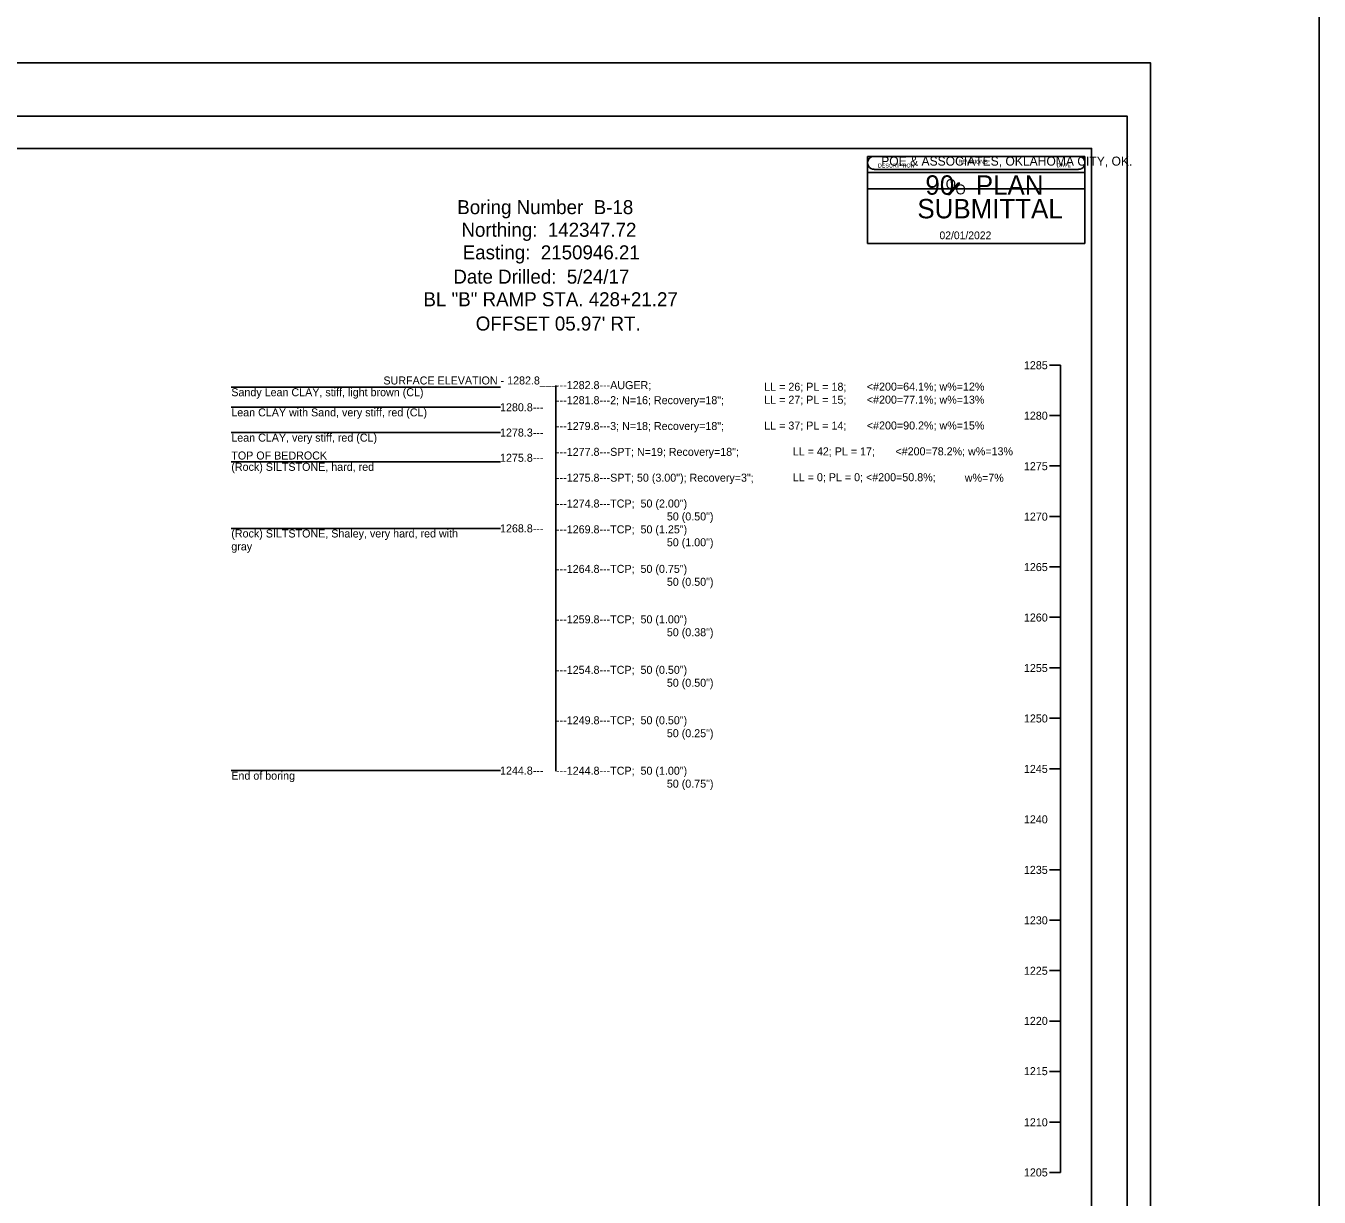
# Model space of a CAD drawing. Extents: x 2150162 to 2150245, y 143729 to 143865.
# Drawn here: x 2150225.21 to 2150245.24, y 143743.1 to 143761.23 of the extents above; entities that cross this region are included whole.
import ezdxf

# ---------------------------------------------------------------- set-up
doc = ezdxf.new("R2010")
doc.units = 0
for name, color, linetype in [('Default', 7, 'Continuous'), ('S', 7, 'Continuous'), ('SHT_Plot_Shape_Full', 7, 'Continuous'), ('SHT_Plot_Shape_Half', 7, 'Continuous'), ('SHT_Sheet_Border', 7, 'Continuous'), ('SHT_Stamp_90_Submit', 7, 'Continuous'), ('SHT_Stamp_Rev_Block', 7, 'Continuous')]:
    doc.layers.add(name, color=color, linetype=linetype)

msp = doc.modelspace()

# ---------------------------------------------------------------- linework, layer by layer
at = {"layer": 'Default'}
msp.add_line((2150241.231, 143743.48), (2150241.231, 143755.98), dxfattribs=at)
for points in [[(2150241.231, 143755.981), (2150241.065, 143755.981)], [(2150228.39, 143755.639), (2150232.557, 143755.639)], [(2150233.416, 143755.664), (2150233.416, 143749.695)], [(2150228.39, 143755.327), (2150232.557, 143755.327)], [(2150241.231, 143755.2), (2150241.065, 143755.2)], [(2150228.39, 143754.936), (2150232.557, 143754.936)], [(2150228.39, 143754.484), (2150232.557, 143754.484)], [(2150241.231, 143754.419), (2150241.065, 143754.419)], [(2150241.231, 143754.419), (2150241.065, 143754.419)], [(2150241.231, 143753.637), (2150241.065, 143753.637)], [(2150228.39, 143753.452), (2150232.557, 143753.452)], [(2150241.231, 143752.856), (2150241.065, 143752.856)], [(2150241.231, 143752.075), (2150241.065, 143752.075)], [(2150241.231, 143751.294), (2150241.065, 143751.294)], [(2150241.231, 143750.512), (2150241.065, 143750.512)], [(2150228.39, 143749.702), (2150232.557, 143749.702)], [(2150241.231, 143749.731), (2150241.065, 143749.731)], [(2150241.231, 143748.167), (2150241.065, 143748.167)], [(2150241.231, 143747.386), (2150241.065, 143747.386)], [(2150241.231, 143746.605), (2150241.065, 143746.605)], [(2150241.231, 143745.823), (2150241.065, 143745.823)], [(2150241.231, 143745.042), (2150241.065, 143745.042)], [(2150241.231, 143744.261), (2150241.065, 143744.261)], [(2150241.231, 143743.48), (2150241.065, 143743.48)]]:
    msp.add_lwpolyline(points, dxfattribs=at)
at = {"layer": 'S'}
msp.add_lwpolyline([(2150203.404, 143865.061), (2150245.24, 143865.061), (2150245.24, 143729.315), (2150203.404, 143729.315)], close=True, dxfattribs=at)
at = {"layer": 'SHT_Plot_Shape_Full'}
msp.add_lwpolyline([(2150206.628, 143760.659), (2150242.628, 143760.659), (2150242.628, 143736.659), (2150206.628, 143736.659)], close=True, dxfattribs=at)
at = {"layer": 'SHT_Plot_Shape_Half'}
msp.add_lwpolyline([(2150208.265, 143759.835), (2150242.265, 143759.835), (2150242.265, 143737.835), (2150208.265, 143737.835)], close=True, dxfattribs=at)
at = {"layer": 'SHT_Sheet_Border'}
msp.add_lwpolyline([(2150241.715, 143738.335), (2150210.215, 143738.335), (2150210.215, 143759.335), (2150241.715, 143759.335)], close=True, dxfattribs=at)
at = {"layer": 'SHT_Stamp_90_Submit'}
for p, q in [((2150238.346, 143759.21), (2150241.512, 143759.21)), ((2150238.246, 143758.96), (2150241.612, 143758.96)), ((2150238.246, 143757.861), (2150238.246, 143758.96)), ((2150238.346, 143759.01), (2150241.512, 143759.01)), ((2150241.612, 143757.861), (2150241.612, 143758.96)), ((2150239.489, 143758.622), (2150239.645, 143758.795)), ((2150239.507, 143758.622), (2150239.662, 143758.795)), ((2150239.512, 143758.622), (2150239.667, 143758.795)), ((2150239.52, 143758.622), (2150239.675, 143758.795)), ((2150239.645, 143758.795), (2150239.675, 143758.795)), ((2150239.489, 143758.622), (2150239.52, 143758.622)), ((2150238.246, 143757.861), (2150241.612, 143757.861))]:
    msp.add_line(p, q, dxfattribs=at)
for centre, start, end in [((2150238.346, 143759.111), 89.9952, 270), ((2150241.512, 143759.111), 270, 90.0048)]:
    msp.add_arc(centre, 0.1, start, end, dxfattribs=at)
at = {"layer": 'SHT_Stamp_Rev_Block'}
for p, q in [((2150238.246, 143759.21), (2150238.246, 143758.71)), ((2150241.612, 143759.21), (2150238.246, 143759.21)), ((2150241.612, 143758.71), (2150241.612, 143759.21)), ((2150241.612, 143758.96), (2150238.246, 143758.96)), ((2150241.612, 143758.71), (2150238.246, 143758.71))]:
    msp.add_line(p, q, dxfattribs=at)

# ---------------------------------------------------------------- texts
at = {"layer": 'Default'}
for s, height, p in [('Boring Number  B-18', 0.217, (2150231.89, 143758.317)), ('Northing:  142347.72', 0.217, (2150231.954, 143757.967)), ('Easting:  2150946.21', 0.217, (2150231.974, 143757.617)), ('Date Drilled:  5/24/17', 0.217, (2150231.829, 143757.241)), ('BL "B" RAMP STA. 428+21.27', 0.217, (2150231.366, 143756.891)), ("OFFSET 05.97' RT.", 0.217, (2150232.176, 143756.515)), ('1285', 0.124, (2150240.667, 143755.916)), ('SURFACE ELEVATION - 1282.8___', 0.124, (2150230.746, 143755.68)), ('---1282.8---AUGER;', 0.124, (2150233.42, 143755.608)), ('LL = 26; PL = 18;', 0.124, (2150236.645, 143755.583)), ('<#200=64.1%; w%=12%', 0.124, (2150238.234, 143755.585)), ('Sandy Lean CLAY, stiff, light brown (CL)', 0.124, (2150228.39, 143755.498)), ('---1281.8---2; N=16; Recovery=18";', 0.124, (2150233.42, 143755.375)), ('LL = 27; PL = 15;', 0.124, (2150236.645, 143755.382)), ('<#200=77.1%; w%=13%', 0.124, (2150238.234, 143755.383)), ('Lean CLAY with Sand, very stiff, red (CL)', 0.124, (2150228.39, 143755.186)), ('1280.8---', 0.124, (2150232.552, 143755.265)), ('---1279.8---3; N=18; Recovery=18";', 0.124, (2150233.42, 143754.975)), ('LL = 37; PL = 14;', 0.124, (2150236.645, 143754.982)), ('<#200=90.2%; w%=15%', 0.124, (2150238.234, 143754.983)), ('1280', 0.124, (2150240.667, 143755.135)), ('Lean CLAY, very stiff, red (CL)', 0.124, (2150228.39, 143754.795)), ('1278.3---', 0.124, (2150232.552, 143754.874)), ('---1277.8---SPT; N=19; Recovery=18";', 0.124, (2150233.42, 143754.575)), ('LL = 42; PL = 17;', 0.124, (2150237.087, 143754.582)), ('<#200=78.2%; w%=13%', 0.124, (2150238.677, 143754.583)), ('TOP OF BEDROCK', 0.124, (2150228.39, 143754.518)), ('1275.8---', 0.124, (2150232.552, 143754.483)), ('(Rock) SILTSTONE, hard, red', 0.124, (2150228.39, 143754.343)), ('---1275.8---SPT; 50 (3.00"); Recovery=3";', 0.124, (2150233.42, 143754.175)), ('LL = 0; PL = 0; <#200=50.8%;', 0.124, (2150237.087, 143754.182)), ('1275', 0.124, (2150240.667, 143754.353)), ('w%=7%', 0.124, (2150239.751, 143754.174)), ('---1274.8---TCP;  50 (2.00")', 0.124, (2150233.42, 143753.775)), ('50 (0.50")', 0.124, (2150235.136, 143753.575)), ('1268.8---', 0.124, (2150232.552, 143753.39)), ('---1269.8---TCP;  50 (1.25")', 0.124, (2150233.42, 143753.375)), ('1270', 0.124, (2150240.667, 143753.572)), ('(Rock) SILTSTONE, Shaley, very hard, red with', 0.124, (2150228.39, 143753.311)), ('50 (1.00")', 0.124, (2150235.136, 143753.175)), ('gray', 0.124, (2150228.39, 143753.111)), ('1265', 0.124, (2150240.667, 143752.791)), ('---1264.8---TCP;  50 (0.75")', 0.124, (2150233.42, 143752.763)), ('50 (0.50")', 0.124, (2150235.136, 143752.563)), ('---1259.8---TCP;  50 (1.00")', 0.124, (2150233.42, 143751.982)), ('1260', 0.124, (2150240.667, 143752.01)), ('50 (0.38")', 0.124, (2150235.136, 143751.782)), ('---1254.8---TCP;  50 (0.50")', 0.124, (2150233.42, 143751.2)), ('1255', 0.124, (2150240.667, 143751.228)), ('50 (0.50")', 0.124, (2150235.136, 143751)), ('---1249.8---TCP;  50 (0.50")', 0.124, (2150233.42, 143750.419)), ('1250', 0.124, (2150240.667, 143750.447)), ('50 (0.25")', 0.124, (2150235.136, 143750.219)), ('1244.8---', 0.124, (2150232.552, 143749.64)), ('---1244.8---TCP;  50 (1.00")', 0.124, (2150233.42, 143749.638)), ('1245', 0.124, (2150240.667, 143749.666)), ('End of boring', 0.124, (2150228.39, 143749.561)), ('50 (0.75")', 0.124, (2150235.136, 143749.438)), ('1240', 0.124, (2150240.667, 143748.885)), ('1235', 0.124, (2150240.667, 143748.103)), ('1230', 0.124, (2150240.667, 143747.322)), ('1225', 0.124, (2150240.667, 143746.541)), ('1220', 0.124, (2150240.667, 143745.765)), ('1215', 0.124, (2150240.667, 143744.987)), ('1210', 0.124, (2150240.667, 143744.195)), ('1205', 0.124, (2150240.667, 143743.419))]:
    msp.add_text(s, height=height, dxfattribs=at).set_placement(p)
at = {"layer": 'SHT_Stamp_90_Submit'}
for s, height, p in [('POE & ASSOCIATES, OKLAHOMA CITY, OK.', 0.14, (2150238.456, 143759.068)), ('90   PLAN', 0.3, (2150239.141, 143758.618)), ('O', 0.153, (2150239.455, 143758.707)), ('O', 0.153, (2150239.607, 143758.623)), ('SUBMITTAL', 0.3, (2150239.017, 143758.252)), ('02/01/2022', 0.12, (2150239.359, 143757.929))]:
    msp.add_text(s, height=height, dxfattribs=at).set_placement(p)
at = {"layer": 'SHT_Stamp_Rev_Block'}
for s, height, p in [('REVISIONS', 0.06, (2150239.654, 143759.098)), ('DESCRIPTION', 0.05999, (2150238.406, 143759.039)), ('DATE', 0.06, (2150241.175, 143759.043))]:
    msp.add_text(s, height=height, dxfattribs=at).set_placement(p)

doc.saveas('drawing.dxf')
